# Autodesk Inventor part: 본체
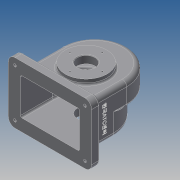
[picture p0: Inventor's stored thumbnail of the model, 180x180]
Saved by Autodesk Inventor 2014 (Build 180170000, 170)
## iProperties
Created: 2017-11
Part Number: 본체
Material: Generic
Document SubType Name: Modeling
Designer: kb543-05
Density: 1 g/cm^3
Appearance: Default
Author: kb543-05
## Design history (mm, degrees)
sketch "스케치1"
  geometry: L1 (58, 0)-(58, -65); L2 (58, -65)-(-58, -65); L3 (-58, -65)-(-58, 0); A1 r 58 centre (0, 0) between (58, 0) and (-58, 0); 1 further point
  constraints: 6 end point, 2 perpendicular, 2 point on circle, 2 tangent, 1 centre point, 1 coincident, 1 vertical
  dimensions: "d0" = 116 diameter of A1; "d1" = 65 distance of L1.start L1.end
extrude "돌출1" new body sketch "스케치1" distance "d2" = 38; taper "d3" = 0 deg
sketch "스케치2"
  geometry: L1 (-58, -65)-(-58, 0) reference; L2 (58, -65)-(-58, -65) reference; L3 (58, 0)-(58, -65) reference; L4 (-58, -23)-(-58, -65); L5 (58, -65)-(58, -23); A1 r 58 centre (0, 0) between (58, 0) and (-58, 0) reference; A2 r 58 centre (0, -23) between (58, -23) and (-58, -23)
  constraints: 4 end point, 2 point on circle, 2 point on line, 1 centre point, 1 parallel, 1 vertical alignment
  dimensions: "d4" = 116 diameter of A2; "d5" = 42 distance from line of A2.centre L2
extrude "돌출2" join sketch "스케치2" distance "d6" = 38; taper "d7" = 0 deg
feature "쉘1" dims "d8" = 5
sketch "스케치3"
  geometry: L1 (133, -93)-(-17, -93); L2 (-17, -93)-(-17, 17); L3 (-17, 17)-(133, 17); L4 (133, 17)-(133, -93); L5 (133, -93)-(-17, 17); L6 (-17, -93)-(133, 17); 1 further point
  constraints: 12 end point, 2 midpoint, 2 parallel, 1 horizontal, 1 perpendicular
  dimensions: "d9" = 150 distance of L2.end L3.end; "d10" = 110 distance of L1.end L2.end
extrude "돌출3" join sketch "스케치3" distance "d11" = 15; taper "d12" = 0 deg
sketch "스케치4"
  geometry: L1 (5, -5)-(111, -5) reference; L2 (5, -71)-(5, -5) reference; L3 (111, -71)-(5, -71) reference; L4 (111, -71)-(111, -5) reference; 1 further point
extrude "돌출4" cut sketch "스케치4" distance "d13" = 20; taper "d14" = 0 deg
fillet "모깎기1" dims "d15" = 12
sketch "스케치6"
  geometry: A1 r 12 centre (-5, 81) between (-5, 93) and (-17, 81) reference; A2 r 12 centre (-5, -5) between (-17, -5) and (-5, -17) reference; A3 r 12 centre (121, -5) between (121, -17) and (133, -5) reference; A4 r 12 centre (121, 81) between (133, 81) and (121, 93) reference; 1 further point
hole "구멍1" sketch "스케치6" at (-5, 81), (121, 81), (121, -5), (-5, -5) diameter "d16" = 5; stored, may be unused: countersink angle "d20" = 90 deg, drill point angle "d22" = 118 deg; dims "d17" = 6, "d18" = 12, "d19" = 5, "d21" = 8
sketch "스케치7"
  geometry: L1 (63, -80)-(-63, -80) reference; C1 r 37.5 at (0, -15); A1 r 58 centre (0, 0) between (58, 0) and (-58, 0) reference
  constraints: 1 centre point, 1 vertical alignment
  dimensions: "d23" = 75 diameter of C1; "d24" = 65 distance from line of C1.centre L1
extrude "돌출5" join sketch "스케치7" distance "d25" = 9; taper "d26" = 0 deg
sketch "스케치8"
  geometry: L1 (63, -80)-(-63, -80) reference; C1 r 31 at (0, -15); 1 further point
  constraints: 1 centre point, 1 vertical alignment
  dimensions: "d27" = 62 diameter of C1; "d28" = 65 distance from line of C1.centre L1
extrude "돌출6" join sketch "스케치8" distance "d29" = 10; taper "d30" = 0 deg
sketch "스케치9"
  geometry: C1 r 31 at (0, 0) reference; C2 r 16 at (0, 0); 1 further point
  constraints: 1 centre point, 1 coincident
  dimensions: "d31" = 32 diameter of C2
extrude "돌출7" cut sketch "스케치9" stored distance "d32" = 10; taper "d33" = 0 deg
node "작업 평면1"
sketch "스케치10"
  geometry: L1 (116, 0)-(0, 0) reference; C1 r 6 at (58, -19); 1 further point
  constraints: 1 centre point, 1 vertical alignment
  dimensions: "d35" = 12 diameter of C1; "d36" = 19 distance from line of C1.centre L1
extrude "돌출8" join sketch "스케치10" stored distance "d37" = 10; taper "d38" = 0 deg
sketch "스케치11"
  geometry: C1 r 6 at (0, 0) reference; 1 further point
hole "구멍2" sketch "스케치11" at (0, 0) diameter "d39" = 4.459; stored, may be unused: countersink angle "d43" = 90 deg, drill point angle "d45" = 118 deg; dims "d40" = 6, "d41" = 12, "d42" = 5, "d44" = 8
sketch "스케치12" dims "d46" = 58
  geometry: C1 r 16 at (0, 0) reference; C2 r 37.5 at (0, 0) reference; 6 further points
  constraints: 2 vertical alignment, 1 coincident, 7 other
  dimensions: "d49" = 360 deg dimension on C1.centre point (0, 29) (derived)
hole "구멍3" sketch "스케치12" at (0, 29), (-29, 0), (0, -29), (29, 0) diameter "d51" = 2.459; stored, may be unused: countersink angle "d55" = 90 deg, drill point angle "d57" = 118 deg; dims "d52" = 6, "d53" = 12, "d54" = 5, "d56" = 8
sketch "스케치13" dims "d58" = 52
  geometry: C1 r 16 at (0, 0) reference; C2 r 31 at (0, 0) reference; 6 further points
  constraints: 2 vertical alignment, 1 coincident, 7 other
  dimensions: "d61" = 360 deg dimension on C1.centre point (0, 26) (derived)
hole "구멍4" sketch "스케치13" at (0, 26), (-26, 0), (0, -26), (26, 0) diameter "d63" = 2.459; stored, may be unused: countersink angle "d67" = 90 deg, drill point angle "d69" = 118 deg; dims "d64" = 6, "d65" = 12, "d66" = 5, "d68" = 8
sketch "스케치14"
  geometry: L1 (0, -65)-(0, 0) reference; L2 (13.113, -36.398)-(62.887, -36.398); L3 (62.887, -36.398)-(62.887, -43.602); L4 (62.887, -43.602)-(13.113, -43.602); L5 (13.113, -43.602)-(13.113, -36.398); L6 (81, -80)-(-5, -80) reference; 3 further points
  constraints: 2 midpoint, 1 horizontal alignment, 1 vertical alignment, 2 other
  dimensions: "d70" = 40 distance from line of L6 point (38, -40); "d71" = 38 distance from line of point (38, -40) L1
feature "엠보싱1" sketch "스케치14" dims "d72" = 0.5, "d73" = 0
fillet "모깎기2" dims "d74" = 8
fillet "모깎기3" dims "d75" = 3
fillet "모깎기4" dims "d76" = 3
chamfer "모따기1" distance "d77" = 1; stored, may be unused: second distance "d78" = 2, angle "d79" = 45 deg
node "솔리드1"
other parameters: "d34" = -144
